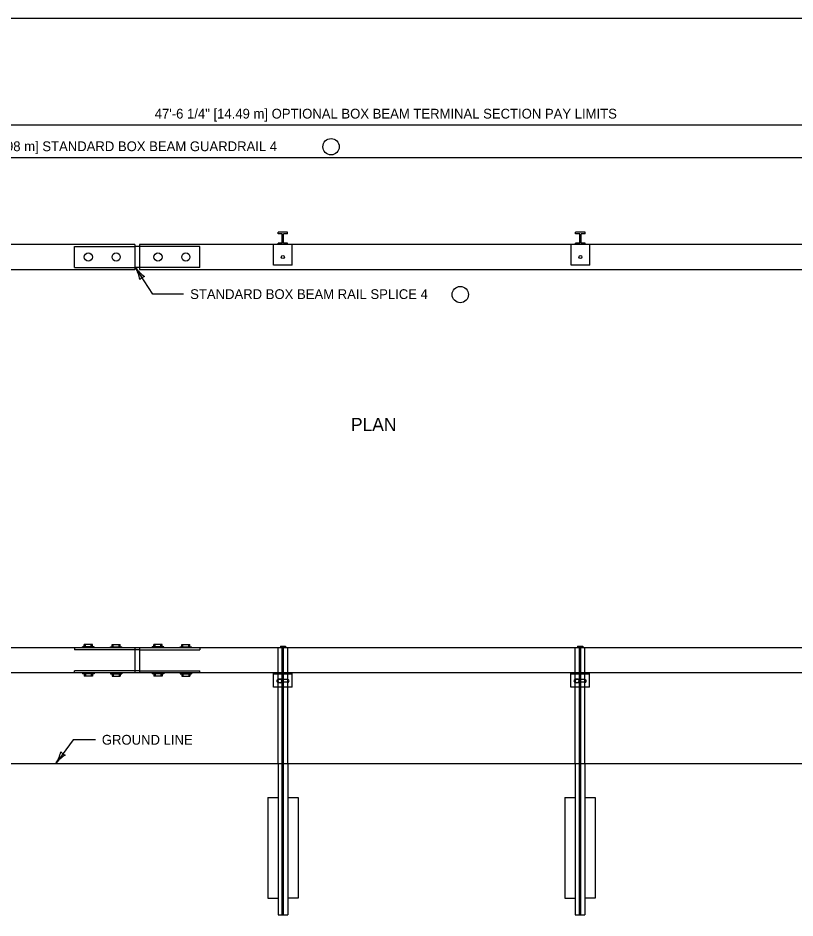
# Model space of a CAD drawing. Extents: x 49991.4 to 50021, y 49987.6 to 50011.4.
# Drawn here: x 50005.97 to 50010.73, y 49993.48 to 49999 of the extents above; entities that cross this region are included whole.
import ezdxf

# ---------------------------------------------------------------- set-up
doc = ezdxf.new("R2010")
doc.units = 0
for name, color, linetype in [('Level 1', 7, 'Continuous'), ('Level 2', 7, 'Continuous'), ('Level 3', 7, 'Continuous'), ('Level 4', 7, 'Continuous')]:
    doc.layers.add(name, color=color, linetype=linetype)

msp = doc.modelspace()

# ---------------------------------------------------------------- linework, layer by layer
at = {"layer": 'Level 1'}
for p, q in [((50007.5633, 49997.6755), (50007.5633, 49997.6847)), ((50007.6224, 49997.6847), (50007.5633, 49997.6847)), ((50007.5883, 49997.6755), (50007.5633, 49997.6755)), ((50007.5883, 49997.6179), (50007.5883, 49997.6755)), ((50007.5974, 49997.6179), (50007.5974, 49997.6755)), ((50007.6224, 49997.6755), (50007.5974, 49997.6755)), ((50007.6224, 49997.6755), (50007.6224, 49997.6847)), ((50009.3888, 49997.6755), (50009.3888, 49997.6847)), ((50009.4479, 49997.6847), (50009.3888, 49997.6847)), ((50009.4138, 49997.6755), (50009.3888, 49997.6755)), ((50009.4138, 49997.6179), (50009.4138, 49997.6755)), ((50009.4229, 49997.6179), (50009.4229, 49997.6755)), ((50009.4479, 49997.6755), (50009.4229, 49997.6755)), ((50009.4479, 49997.6755), (50009.4479, 49997.6847)), ((50007.5883, 49997.6179), (50007.5633, 49997.6179)), ((50007.5633, 49997.6087), (50007.5633, 49997.6179)), ((50007.6224, 49997.6179), (50007.5974, 49997.6179)), ((50007.6224, 49997.6087), (50007.6224, 49997.6179)), ((50009.4138, 49997.6179), (50009.3888, 49997.6179)), ((50009.3888, 49997.6087), (50009.3888, 49997.6179)), ((50009.4479, 49997.6179), (50009.4229, 49997.6179)), ((50009.4479, 49997.6087), (50009.4479, 49997.6179)), ((50006.6846, 49997.6087), (50001.2265, 49997.6087)), ((50006.6846, 49997.6087), (50006.6846, 49997.4569)), ((50006.713, 49997.5975), (50006.6846, 49997.5975)), ((50006.713, 49997.6087), (50006.713, 49997.4568)), ((50012.2286, 49997.6087), (50006.713, 49997.6087)), ((50006.713, 49997.468), (50006.6846, 49997.4681)), ((50012.2287, 49995.1348), (50001.2264, 49995.1348)), ((50006.4352, 49995.142), (50006.3642, 49995.142)), ((50006.3642, 49995.1349), (50006.3642, 49995.142)), ((50006.375, 49995.142), (50006.375, 49995.1562)), ((50006.4248, 49995.1562), (50006.375, 49995.1562)), ((50006.382, 49995.142), (50006.382, 49995.1562)), ((50006.4176, 49995.142), (50006.4176, 49995.1562)), ((50006.4248, 49995.142), (50006.4248, 49995.1562)), ((50006.4352, 49995.1349), (50006.4352, 49995.142)), ((50006.535, 49995.142), (50006.6062, 49995.142)), ((50006.535, 49995.1349), (50006.535, 49995.142)), ((50006.5458, 49995.1562), (50006.5956, 49995.1562)), ((50006.5458, 49995.142), (50006.5458, 49995.1562)), ((50006.5528, 49995.142), (50006.5528, 49995.1562)), ((50006.5886, 49995.142), (50006.5886, 49995.1562)), ((50006.5956, 49995.142), (50006.5956, 49995.1562)), ((50006.6062, 49995.1349), (50006.6062, 49995.142)), ((50006.6846, 49995.1348), (50006.6846, 49994.9829)), ((50006.713, 49995.1348), (50006.6846, 49995.1348)), ((50006.713, 49995.1348), (50006.713, 49994.9829)), ((50006.8626, 49995.142), (50006.7914, 49995.142)), ((50006.7914, 49995.1349), (50006.7914, 49995.142)), ((50006.852, 49995.1562), (50006.8022, 49995.1562)), ((50006.8022, 49995.142), (50006.8022, 49995.1562)), ((50006.8092, 49995.142), (50006.8092, 49995.1562)), ((50006.845, 49995.142), (50006.845, 49995.1562)), ((50006.852, 49995.142), (50006.852, 49995.1562)), ((50006.8626, 49995.1349), (50006.8626, 49995.142)), ((50006.9624, 49995.142), (50007.0336, 49995.142)), ((50006.9624, 49995.1349), (50006.9624, 49995.142)), ((50006.973, 49995.1562), (50007.023, 49995.1562)), ((50006.973, 49995.142), (50006.973, 49995.1562)), ((50006.9802, 49995.142), (50006.9802, 49995.1562)), ((50007.0158, 49995.142), (50007.0158, 49995.1562)), ((50007.023, 49995.142), (50007.023, 49995.1562)), ((50007.0336, 49995.1349), (50007.0336, 49995.142)), ((50007.5778, 49995.146), (50007.609, 49995.146)), ((50007.5778, 49995.146), (50007.5778, 49995.1348)), ((50007.5846, 49995.146), (50007.5846, 49995.1348)), ((50007.6022, 49995.146), (50007.6022, 49995.1348)), ((50007.609, 49995.146), (50007.609, 49995.1348)), ((50009.401, 49995.146), (50009.4322, 49995.146)), ((50009.401, 49995.146), (50009.401, 49995.1348)), ((50009.4078, 49995.146), (50009.4078, 49995.1348)), ((50009.4254, 49995.146), (50009.4254, 49995.1348)), ((50009.4322, 49995.146), (50009.4322, 49995.1348)), ((50006.713, 49995.1236), (50006.6846, 49995.1236)), ((50012.2287, 49994.9829), (50001.2264, 49994.9829)), ((50006.3642, 49994.9829), (50006.3642, 49994.9758)), ((50006.4352, 49994.9758), (50006.3642, 49994.9758)), ((50006.375, 49994.9758), (50006.375, 49994.9616)), ((50006.382, 49994.9758), (50006.382, 49994.9616)), ((50006.4176, 49994.9758), (50006.4176, 49994.9616)), ((50006.4248, 49994.9758), (50006.4248, 49994.9616)), ((50006.4352, 49994.9829), (50006.4352, 49994.9758)), ((50006.535, 49994.9829), (50006.535, 49994.9758)), ((50006.535, 49994.9758), (50006.6062, 49994.9758)), ((50006.5458, 49994.9758), (50006.5458, 49994.9616)), ((50006.5528, 49994.9758), (50006.5528, 49994.9616)), ((50006.5886, 49994.9758), (50006.5886, 49994.9616)), ((50006.5956, 49994.9758), (50006.5956, 49994.9616)), ((50006.6062, 49994.9829), (50006.6062, 49994.9758)), ((50006.713, 49994.9941), (50006.6846, 49994.9941)), ((50006.713, 49994.9829), (50006.6846, 49994.9829)), ((50006.7914, 49994.9829), (50006.7914, 49994.9758)), ((50006.8626, 49994.9758), (50006.7914, 49994.9758)), ((50006.8022, 49994.9758), (50006.8022, 49994.9616)), ((50006.8092, 49994.9758), (50006.8092, 49994.9616)), ((50006.845, 49994.9758), (50006.845, 49994.9616)), ((50006.852, 49994.9758), (50006.852, 49994.9616)), ((50006.8626, 49994.9829), (50006.8626, 49994.9758)), ((50006.9624, 49994.9829), (50006.9624, 49994.9758)), ((50006.9624, 49994.9758), (50007.0336, 49994.9758)), ((50006.973, 49994.9758), (50006.973, 49994.9616)), ((50006.9802, 49994.9758), (50006.9802, 49994.9616)), ((50007.0158, 49994.9758), (50007.0158, 49994.9616)), ((50007.023, 49994.9758), (50007.023, 49994.9616)), ((50007.0336, 49994.9829), (50007.0336, 49994.9758)), ((50007.5364, 49994.8944), (50007.5364, 49994.9829)), ((50007.6504, 49994.9734), (50007.5364, 49994.9734)), ((50007.6504, 49994.8944), (50007.6504, 49994.9829)), ((50009.3596, 49994.8944), (50009.3596, 49994.9829)), ((50009.4736, 49994.9734), (50009.3596, 49994.9734)), ((50009.4736, 49994.8944), (50009.4736, 49994.9829)), ((50006.4248, 49994.9616), (50006.375, 49994.9616)), ((50006.5458, 49994.9616), (50006.5956, 49994.9616)), ((50006.852, 49994.9616), (50006.8022, 49994.9616)), ((50006.973, 49994.9616), (50007.023, 49994.9616)), ((50007.6228, 49994.9402), (50007.5852, 49994.9402)), ((50007.6234, 49994.9244), (50007.5854, 49994.9244)), ((50009.446, 49994.9402), (50009.4084, 49994.9402)), ((50009.4466, 49994.9244), (50009.4086, 49994.9244)), ((50007.6504, 49994.8944), (50007.5364, 49994.8944)), ((50007.5636, 49994.4258), (50007.5636, 49994.8943)), ((50007.6228, 49994.4258), (50007.6228, 49994.8943)), ((50009.4736, 49994.8944), (50009.3596, 49994.8944)), ((50009.3868, 49994.4258), (50009.3868, 49994.8943)), ((50009.446, 49994.4258), (50009.446, 49994.8943)), ((49999.8098, 49994.4259), (50016.5942, 49994.4259))]:
    msp.add_line(p, q, dxfattribs=at)
for points in [[(49999.3835, 49998.9992), (50016.7501, 49998.9992), (50016.7501, 49987.7988), (49999.3835, 49987.7988)], [(50007.5682, 49994.9431), (50007.5806, 49994.943), (50007.5866, 49994.9322), (50007.5802, 49994.9216), (50007.568, 49994.9218), (50007.562, 49994.9325)], [(50009.3914, 49994.9431), (50009.4038, 49994.943), (50009.4098, 49994.9322), (50009.4034, 49994.9216), (50009.3912, 49994.9218), (50009.3852, 49994.9325)]]:
    msp.add_lwpolyline(points, close=True, dxfattribs=at)
for points in [[(50003.915, 49997.4568), (50006.6846, 49997.4568)], [(50006.713, 49997.4568), (50012.2286, 49997.4568)]]:
    msp.add_lwpolyline(points, dxfattribs=at)
for centre, radius in [((50006.3998, 49997.5327), 0.0249), ((50006.5707, 49997.5327), 0.0249), ((50006.8271, 49997.5327), 0.0249), ((50006.998, 49997.5327), 0.0249), ((50007.593, 49997.5328), 0.00948), ((50009.4185, 49997.5328), 0.00948), ((50007.5744, 49994.9322), 0.0135), ((50009.3976, 49994.9322), 0.0135)]:
    msp.add_circle(centre, radius, dxfattribs=at)
for centre, start, end in [((50007.5633, 49994.9323), 88.9909, 270.2781), ((50007.6234, 49994.9323), 269.7219, 91.0091), ((50009.3865, 49994.9323), 88.9909, 270.2781), ((50009.4466, 49994.9323), 269.7219, 91.0091)]:
    msp.add_arc(centre, 0.00794, start, end, dxfattribs=at)
at = {"layer": 'Level 2'}
for centre in [(50007.8885, 49998.2096), (50008.6814, 49997.3026)]:
    msp.add_circle(centre, 0.05, dxfattribs=at)
at = {"layer": 'Level 3'}
for p, q in [((50015.7531, 49998.3423), (50001.2124, 49998.3423)), ((50012.2286, 49998.1423), (50001.2124, 49998.1423)), ((50006.796, 49997.3052), (50006.6893, 49997.4681)), ((50006.9845, 49997.3052), (50006.796, 49997.3052)), ((50006.3063, 49994.5714), (50006.1997, 49994.4259)), ((50006.4428, 49994.5714), (50006.3063, 49994.5714))]:
    msp.add_line(p, q, dxfattribs=at)
for centre, radius, start, end in [((50006.4971, 49997.3563), 0.2223, 10.0153, 30.1988), ((50006.8792, 49997.603), 0.233, 215.3866, 234.6365), ((50006.7583, 49997.36), 0.0548, 104.6981, 140.4205), ((50006.0052, 49994.5541), 0.233, 326.5991, 345.8489), ((50006.3735, 49994.2872), 0.2223, 121.2278, 141.4113), ((50006.2755, 49994.5293), 0.0548, 215.9106, 251.633)]:
    msp.add_arc(centre, radius, start, end, dxfattribs=at)
at = {"layer": 'Level 4'}
for p, q in [((50006.3142, 49997.468), (50006.3142, 49997.5975)), ((50006.3142, 49997.5975), (50006.6846, 49997.5975)), ((50007.0834, 49997.5975), (50006.713, 49997.5975)), ((50007.0834, 49997.4681), (50007.0834, 49997.5975)), ((50007.5358, 49997.4821), (50007.5358, 49997.6087)), ((50007.6498, 49997.4821), (50007.6498, 49997.6087)), ((50009.3613, 49997.4821), (50009.3613, 49997.6087)), ((50009.4753, 49997.4821), (50009.4753, 49997.6087)), ((50006.3142, 49997.468), (50006.6846, 49997.4681)), ((50007.0834, 49997.4681), (50006.713, 49997.468)), ((50007.6498, 49997.4821), (50007.5358, 49997.4821)), ((50009.4753, 49997.4821), (50009.3613, 49997.4821)), ((50006.3144, 49995.1348), (50006.3144, 49995.1236)), ((50007.0836, 49995.1348), (50007.0836, 49995.1236)), ((50007.5636, 49994.8944), (50007.5636, 49995.1348)), ((50007.5886, 49993.498), (50007.5886, 49995.1348)), ((50007.5978, 49993.498), (50007.5978, 49995.1348)), ((50007.6228, 49994.8944), (50007.6228, 49995.1348)), ((50009.3868, 49994.8944), (50009.3868, 49995.1348)), ((50009.4118, 49993.498), (50009.4118, 49995.1348)), ((50009.421, 49993.498), (50009.421, 49995.1348)), ((50009.446, 49994.8944), (50009.446, 49995.1348)), ((50006.6846, 49995.1236), (50006.3144, 49995.1236)), ((50006.713, 49995.1236), (50007.0836, 49995.1236)), ((50006.6846, 49994.9941), (50006.3144, 49994.9941)), ((50006.3144, 49994.9829), (50006.3144, 49994.9941)), ((50006.713, 49994.9941), (50007.0836, 49994.9941)), ((50007.0836, 49994.9829), (50007.0836, 49994.9941)), ((50007.5636, 49994.4258), (50007.5636, 49993.498)), ((50007.6228, 49994.4258), (50007.6228, 49993.498)), ((50009.3868, 49994.4258), (50009.3868, 49993.498)), ((50009.446, 49994.4258), (50009.446, 49993.498)), ((50007.5004, 49994.2178), (50007.5636, 49994.2178)), ((50007.5004, 49994.2178), (50007.5004, 49993.5993)), ((50007.6228, 49994.2178), (50007.686, 49994.2178)), ((50007.686, 49994.2178), (50007.686, 49993.5993)), ((50009.3236, 49994.2178), (50009.3868, 49994.2178)), ((50009.3236, 49994.2178), (50009.3236, 49993.5993)), ((50009.446, 49994.2178), (50009.5092, 49994.2178)), ((50009.5092, 49994.2178), (50009.5092, 49993.5993)), ((50007.5004, 49993.5993), (50007.5636, 49993.5993)), ((50007.6228, 49993.6027), (50007.686, 49993.6027)), ((50009.3236, 49993.5993), (50009.3868, 49993.5993)), ((50009.446, 49993.6027), (50009.5092, 49993.6027)), ((50007.5636, 49993.498), (50007.6228, 49993.498)), ((50009.3868, 49993.498), (50009.446, 49993.498))]:
    msp.add_line(p, q, dxfattribs=at)

# ---------------------------------------------------------------- texts
at = {"layer": 'Level 2'}
for s, height, p in [('47\'-6 1/4" [14.49 m] OPTIONAL BOX BEAM TERMINAL SECTION PAY LIMITS', 0.06, (50006.807, 49998.3823)), ('36\'-0" [10.98 m] STANDARD BOX BEAM GUARDRAIL 4', 0.06, (50005.5342, 49998.1823)), ('STANDARD BOX BEAM RAIL SPLICE 4', 0.06, (50007.0245, 49997.2752)), ('PLAN', 0.08, (50008.0104, 49996.4657)), ('GROUND LINE', 0.06, (50006.4828, 49994.5414))]:
    msp.add_text(s, height=height, dxfattribs=at).set_placement(p)

doc.saveas('drawing.dxf')
